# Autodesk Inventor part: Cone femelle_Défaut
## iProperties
Shininess: 64.0
Length Units: 11269
Angle Units: 11279
Time Units: 11290
Mass Units: 11283
Length Display Precision: 3
Angle Display Precision: 2
Compacted: True
Part Number: Cone femelle_Défaut
Document SubType Name: Modeling
Created: 2006-11
Material: Par défaut
Designer: profs_sti
Density: 0.0
Volumn: 0.0
Area: 0.0
PropertySet Name: Model Information
Control State: 0
Master: False
Checked Out: False
Author: profs_sti
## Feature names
1. Base1
